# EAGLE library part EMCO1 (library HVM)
EMCO 9730 HV GENERATOR
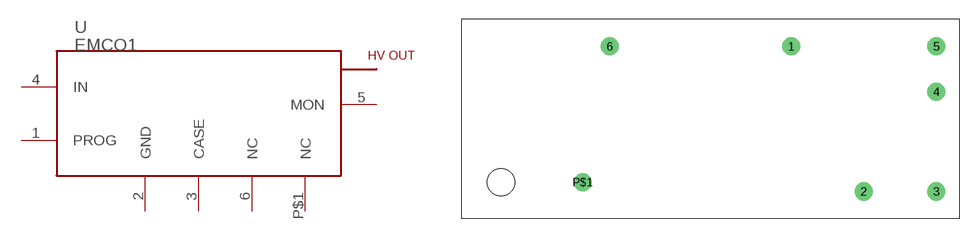
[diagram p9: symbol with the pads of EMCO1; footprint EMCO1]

Designator prefix U

## EMCO1  [EMCO1]
1  PROG  pas
2  GND  pas
3  CASE  pas
4  IN  pas
5  MON  pas
6  NC  nc
P$1  NC  nc

## Footprint EMCO1 (pad centres in mm)
drill 1.27 pad 2.54 round: 1 37.338,24.13; 2 47.498,3.81; 3 57.658,3.81; 4 57.658,17.78; 5 57.658,24.13; 6 11.938,24.13; P$1 8.128,5.08
hole 3.81 at -3.302,5.08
